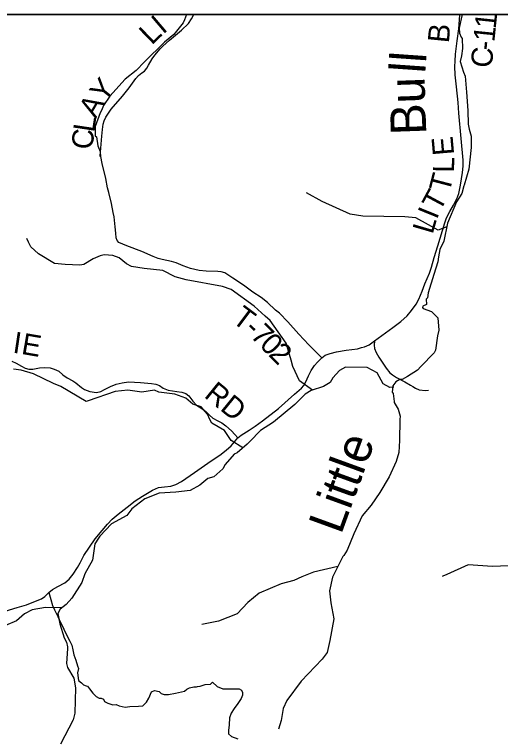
# Model space of a CAD drawing. Extents: x -1.8 to 75.7, y -2 to 25.
# Drawn here: x 45.252 to 46.551, y 20.577 to 22.512 of the extents above; entities that cross this region are included whole.
import ezdxf

# ---------------------------------------------------------------- set-up
doc = ezdxf.new("R2010")
doc.units = 0
for name, color, linetype in [('GM_X_County_Road', 7, 'Continuous'), ('GM_X_County_Road_Text', 7, 'Continuous'), ('GM_X_Minor_River', 7, 'Continuous'), ('GM_X_Minor_River_Text', 7, 'Continuous'), ('GM_X_Township', 7, 'Continuous'), ('GM_X_Township_Road', 7, 'Continuous'), ('GM_X_Township_Road_Text', 7, 'Continuous'), ('GM_X_Township_ROW', 7, 'Continuous'), ('SH_Data', 7, 'Continuous')]:
    doc.layers.add(name, color=color, linetype=linetype)

msp = doc.modelspace()

# ---------------------------------------------------------------- linework, layer by layer
at = {"layer": 'GM_X_County_Road'}
for points in [[(46.0729, 21.5947), (46.0824, 21.6016), (46.0951, 21.6065), (46.1123, 21.6108), (46.1385, 21.6148), (46.1687, 21.619), (46.1795, 21.6219), (46.1875, 21.6242), (46.1995, 21.6296), (46.2137, 21.6398), (46.2632, 21.6759), (46.2842, 21.6917), (46.3007, 21.7068), (46.3127, 21.7211), (46.325, 21.7379), (46.3323, 21.7511), (46.3408, 21.773), (46.3481, 21.7921), (46.3606, 21.8206), (46.3663, 21.8371), (46.3736, 21.8629), (46.3828, 21.8937), (46.4014, 21.955), (46.4063, 21.9683), (46.4148, 21.9859), (46.4245, 22.0029), (46.4337, 22.0194), (46.4391, 22.0336), (46.4438, 22.056), (46.4467, 22.0729), (46.4493, 22.0897), (46.4504, 22.1067), (46.4507, 22.1229), (46.445, 22.1809), (46.4396, 22.2484), (46.4372, 22.2767), (46.4328, 22.3191), (46.4297, 22.351), (46.4283, 22.3731), (46.429, 22.3877), (46.4306, 22.4057), (46.4351, 22.442), (46.4389, 22.4738), (46.442, 22.5101), (46.4422, 22.5121)], [(45.2266, 20.9177), (45.2587, 20.927), (45.2836, 20.9342), (45.3084, 20.944), (45.3243, 20.9507), (45.3331, 20.957), (45.3438, 20.9679), (45.3538, 20.9754), (45.3677, 20.9833), (45.3866, 20.9937), (45.398, 21.0033), (45.4091, 21.0165), (45.4203, 21.034), (45.4275, 21.047), (45.4376, 21.0662), (45.4519, 21.0886), (45.4677, 21.1107), (45.4862, 21.1336), (45.5007, 21.1499), (45.5131, 21.1639), (45.5289, 21.177), (45.5531, 21.1958), (45.5747, 21.2123), (45.5935, 21.2251), (45.6205, 21.2412), (45.6363, 21.2479), (45.6524, 21.2498), (45.6694, 21.2519), (45.6828, 21.2558), (45.6977, 21.2637), (45.7326, 21.2879), (45.777, 21.3191), (45.8008, 21.3349), (45.8177, 21.3479), (45.831, 21.3595), (45.8487, 21.3809), (45.8572, 21.3877), (45.8786, 21.4012), (45.8951, 21.4118), (45.9149, 21.4259), (45.9571, 21.4594), (46.0003, 21.4971), (46.0189, 21.5134), (46.0251, 21.5209), (46.0307, 21.5308), (46.0376, 21.5469), (46.0444, 21.5606), (46.0536, 21.574), (46.0611, 21.5827), (46.0729, 21.5947)]]:
    msp.add_lwpolyline(points, dxfattribs=at)
at = {"layer": 'GM_X_Minor_River'}
for points in [[(45.7119, 22.5121), (45.706, 22.498), (45.703, 22.49), (45.6773, 22.4584), (45.6524, 22.4382), (45.5991, 22.3856), (45.5769, 22.3624)], [(46.4481, 22.5121), (46.4454, 22.5006), (46.4401, 22.4751), (46.4409, 22.4622), (46.4458, 22.4511), (46.4485, 22.4481), (46.4493, 22.4211), (46.4459, 22.4017), (46.4429, 22.3865), (46.4516, 22.3577), (46.4558, 22.347), (46.46, 22.3048), (46.463, 22.2554), (46.4638, 22.2189), (46.4672, 22.206), (46.4722, 22.1867), (46.4718, 22.1563), (46.4658, 22.0988), (46.4534, 22.0559), (46.4526, 22.054), (46.4474, 22.0338), (46.4326, 22.011), (46.4089, 21.9543), (46.3995, 21.9067), (46.3882, 21.8839), (46.3851, 21.8649), (46.3833, 21.8508), (46.372, 21.817), (46.3576, 21.7686), (46.3554, 21.755), (46.352, 21.7515), (46.3528, 21.7375), (46.3433, 21.7329), (46.3422, 21.7287), (46.3441, 21.726), (46.366, 21.7181), (46.3827, 21.7014), (46.3861, 21.6687), (46.382, 21.6535), (46.3771, 21.6147), (46.3737, 21.6075), (46.3374, 21.5713), (46.3287, 21.5618), (46.3019, 21.5446), (46.2879, 21.5366), (46.2819, 21.537), (46.2706, 21.5305), (46.263, 21.5198), (46.2608, 21.5027), (46.2638, 21.4993), (46.2661, 21.4776), (46.2668, 21.475), (46.2774, 21.4571), (46.282, 21.4385), (46.2812, 21.4302), (46.2805, 21.3739), (46.2791, 21.3412), (46.2715, 21.3172), (46.253, 21.2765), (46.2281, 21.2343), (46.2051, 21.2008), (46.1813, 21.1726), (46.1583, 21.1242), (46.1406, 21.0809), (46.1315, 21.0664), (46.1296, 21.0634), (46.1221, 21.0496), (46.1016, 21.0086)], [(45.5769, 22.3624), (45.5478, 22.3391), (45.5066, 22.2938), (45.4893, 22.2687), (45.484, 22.2553), (45.4806, 22.2496), (45.4674, 22.2131), (45.4678, 22.1876), (45.4712, 22.185), (45.4746, 22.1611), (45.4807, 22.1462), (45.4803, 22.1337), (45.4807, 22.1337)], [(46.4069, 21.9444), (46.3838, 21.9355), (46.3244, 21.969), (46.295, 21.971), (46.1831, 21.9731), (46.1485, 21.9787), (46.0743, 22.0126), (46.0319, 22.0352)], [(46.048, 21.508), (46.0137, 21.533), (45.996, 21.5712), (45.9912, 21.5884), (45.9775, 21.6341), (45.9354, 21.6939), (45.9214, 21.7061), (45.892, 21.7325), (45.831, 21.7769), (45.8078, 21.7853), (45.7104, 21.8028), (45.6808, 21.8113), (45.648, 21.8276), (45.5983, 21.8337), (45.5649, 21.839), (45.5515, 21.8455), (45.5312, 21.8621), (45.5147, 21.8683), (45.4917, 21.8698), (45.4807, 21.8671), (45.4623, 21.8593), (45.4376, 21.8438), (45.4266, 21.8418), (45.387, 21.8439), (45.3591, 21.847), (45.3164, 21.8723), (45.2958, 21.8912), (45.289, 21.9035), (45.2851, 21.9132)], [(45.8616, 21.3538), (45.8308, 21.3733), (45.8128, 21.4008), (45.7793, 21.4197), (45.774, 21.4298), (45.7672, 21.4436), (45.7508, 21.4639), (45.7283, 21.4707), (45.7095, 21.4869), (45.68, 21.4973), (45.6375, 21.5032), (45.6259, 21.5078), (45.5925, 21.5028), (45.5793, 21.5043), (45.5545, 21.5081), (45.5211, 21.5046), (45.4485, 21.48), (45.4436, 21.4782), (45.3756, 21.5176), (45.3558, 21.5258), (45.3029, 21.5518), (45.27, 21.562), (45.2496, 21.5642)], [(46.2657, 21.5163), (46.2547, 21.5155), (46.2372, 21.5251), (46.2207, 21.5549), (46.1943, 21.569), (46.1361, 21.5698), (46.1204, 21.5611), (46.1024, 21.5408), (46.0956, 21.5289), (46.0779, 21.5177), (46.0447, 21.507), (46.0289, 21.4976), (46.0008, 21.4696), (45.9438, 21.4225), (45.9088, 21.4004), (45.8803, 21.3706), (45.8733, 21.3643), (45.8469, 21.3405), (45.8392, 21.3373), (45.8145, 21.3092), (45.8085, 21.298), (45.7848, 21.2767), (45.7684, 21.272), (45.7475, 21.254), (45.721, 21.2404), (45.6834, 21.2359), (45.6384, 21.2332), (45.6001, 21.2181), (45.5653, 21.1907), (45.5523, 21.1733), (45.5108, 21.1514), (45.4795, 21.1182), (45.4767, 21.113), (45.4668, 21.0977), (45.4602, 21.0535), (45.4398, 21.0173), (45.432, 20.9944), (45.4054, 20.9527), (45.3901, 20.935), (45.3742, 20.9226), (45.3675, 20.9114), (45.373, 20.8835), (45.3844, 20.8463), (45.3912, 20.8347), (45.3931, 20.8225), (45.3933, 20.8175), (45.3906, 20.7781), (45.3937, 20.7674), (45.4102, 20.7388), (45.4151, 20.7124), (45.4127, 20.6452), (45.4087, 20.6268), (45.3747, 20.5625)], [(47.1715, 21.1353), (47.0815, 21.1308), (47.0262, 21.1108), (47.0011, 21.1099), (46.9449, 21.1286), (46.9121, 21.1478), (46.8729, 21.1635), (46.8395, 21.1713), (46.8129, 21.1735), (46.7492, 21.1678), (46.7182, 21.149), (46.6173, 21.0764), (46.5939, 21.0542), (46.5716, 21.0389), (46.5287, 21.0368), (46.4638, 21.0418), (46.407, 21.0156), (46.3964, 21.0107), (46.3945, 21.0103)], [(46.1156, 21.0366), (46.0511, 21.0214), (46.0194, 21.0091), (45.9983, 20.9996), (45.9648, 20.9907), (45.9058, 20.966), (45.8752, 20.9404), (45.8467, 20.9106), (45.797, 20.8909), (45.7521, 20.8821)], [(46.1016, 21.0086), (46.0935, 20.9722), (46.0971, 20.9402), (46.1052, 20.8974), (46.0944, 20.8393), (46.087, 20.8076), (46.0736, 20.789), (46.0178, 20.7308), (45.9796, 20.6792), (45.9702, 20.6571), (45.9643, 20.6258), (45.9572, 20.6025)], [(45.3787, 20.9261), (45.3347, 20.9276), (45.2993, 20.9215), (45.2782, 20.9108), (45.2572, 20.8914), (45.2281, 20.879)]]:
    msp.add_lwpolyline(points, dxfattribs=at)
at = {"layer": 'GM_X_Township'}
msp.add_lwpolyline([(48.1876, 22.5121), (43.8002, 22.5121), (43.8002, 18.978)], dxfattribs=at)
at = {"layer": 'GM_X_Township_Road'}
for points in [[(46.0729, 21.5947), (46.0611, 21.6058), (46.0387, 21.6291), (46.0116, 21.6576), (45.9825, 21.6907), (45.96, 21.7142), (45.9494, 21.7222), (45.928, 21.7424), (45.9112, 21.7558), (45.8889, 21.7704), (45.8636, 21.7889), (45.8356, 21.8073), (45.8138, 21.8215), (45.8041, 21.8246), (45.795, 21.8251), (45.7641, 21.8262), (45.7452, 21.8275), (45.7219, 21.8331), (45.7028, 21.8404), (45.6841, 21.848), (45.6712, 21.852), (45.6466, 21.8571), (45.6354, 21.86), (45.6223, 21.8653), (45.5919, 21.8788), (45.5518, 21.8943), (45.531, 21.9028), (45.5266, 21.908), (45.5237, 21.9148), (45.5226, 21.9277), (45.5213, 21.9446), (45.5184, 21.9713), (45.5159, 21.983), (45.5115, 22.0073), (45.5044, 22.0361), (45.5008, 22.0492), (45.4962, 22.0739), (45.4866, 22.1137), (45.4826, 22.1326), (45.4817, 22.1439), (45.4835, 22.1657), (45.4855, 22.1868), (45.4871, 22.2045), (45.4891, 22.219), (45.4915, 22.2281), (45.4962, 22.2376), (45.503, 22.2487), (45.5106, 22.2592), (45.5406, 22.2938), (45.5586, 22.3165), (45.5764, 22.3412), (45.5835, 22.3492), (45.5921, 22.3563), (45.5992, 22.3609), (45.6055, 22.3685), (45.6103, 22.3767), (45.6199, 22.394), (45.6266, 22.4031), (45.6408, 22.42), (45.6479, 22.4278), (45.6657, 22.4431), (45.6981, 22.4705), (45.7165, 22.4882), (45.7248, 22.5004), (45.7313, 22.5121)], [(46.2137, 21.6398), (46.2125, 21.6287), (46.2142, 21.6197), (46.2179, 21.6091), (46.2255, 21.5964), (46.2453, 21.5667), (46.2552, 21.5549), (46.262, 21.5492), (46.2729, 21.5424), (46.2948, 21.5301), (46.3101, 21.5212)], [(45.2452, 21.5853), (45.2563, 21.5801), (45.2709, 21.5727), (45.2802, 21.5673), (45.2899, 21.5639), (45.301, 21.5642), (45.319, 21.5675), (45.3329, 21.5686), (45.3475, 21.5678), (45.3583, 21.5645), (45.3707, 21.5588), (45.3807, 21.5495), (45.3923, 21.5413), (45.4077, 21.5333), (45.4154, 21.5279), (45.4311, 21.5153), (45.4391, 21.5102), (45.453, 21.5044), (45.4712, 21.502), (45.4828, 21.5045), (45.4923, 21.5097), (45.5083, 21.5182), (45.5234, 21.5243), (45.5394, 21.5282), (45.5569, 21.5305), (45.589, 21.5285), (45.6183, 21.5259), (45.6296, 21.5238), (45.6391, 21.5202), (45.6489, 21.5133), (45.6623, 21.5081), (45.6855, 21.5043), (45.6993, 21.5025), (45.7098, 21.4989), (45.7173, 21.493), (45.7281, 21.4788), (45.7384, 21.4683), (45.7528, 21.4588), (45.7631, 21.4516), (45.7731, 21.441), (45.7818, 21.4336), (45.7952, 21.4264), (45.8055, 21.4205), (45.8163, 21.4125), (45.8317, 21.3999), (45.841, 21.3901), (45.8487, 21.3809)], [(45.3438, 20.9679), (45.3487, 20.9484), (45.3533, 20.9328), (45.3543, 20.9308)]]:
    msp.add_lwpolyline(points, dxfattribs=at)
at = {"layer": 'GM_X_Township_ROW'}
for points in [[(46.3101, 21.5212), (46.3163, 21.5176), (46.3236, 21.5139), (46.333, 21.5094), (46.3502, 21.507), (46.3585, 21.508)], [(45.3543, 20.9308), (45.3591, 20.9209), (45.3673, 20.9033), (45.3759, 20.8854), (45.3808, 20.8754), (45.3863, 20.8633), (45.3994, 20.8375), (45.4055, 20.8268), (45.4074, 20.8147), (45.4104, 20.8006), (45.4159, 20.7865), (45.4206, 20.7713), (45.423, 20.7648), (45.4204, 20.7525), (45.423, 20.7326), (45.4308, 20.7261), (45.4359, 20.7205), (45.4434, 20.7183), (45.4473, 20.7169), (45.4521, 20.7098), (45.4611, 20.6984), (45.4704, 20.69), (45.4782, 20.6853), (45.4833, 20.6848), (45.4895, 20.6821), (45.4922, 20.6758), (45.5014, 20.6717), (45.5144, 20.667), (45.5233, 20.668), (45.5318, 20.6649), (45.5472, 20.6608), (45.5598, 20.6628), (45.5828, 20.6634), (45.5951, 20.6643), (45.6047, 20.6743), (45.6106, 20.6847), (45.6179, 20.7025), (45.6264, 20.7053), (45.6382, 20.703), (45.644, 20.6973), (45.6516, 20.6953), (45.6631, 20.6953), (45.6825, 20.6987), (45.7065, 20.704), (45.7121, 20.7093), (45.7197, 20.7129), (45.7312, 20.7155), (45.7379, 20.7154), (45.7412, 20.7161), (45.7479, 20.7174), (45.7614, 20.7218), (45.7753, 20.7229), (45.7807, 20.7277), (45.7935, 20.7164), (45.8083, 20.7105), (45.8397, 20.7103), (45.8525, 20.7101), (45.8584, 20.7068), (45.8614, 20.7003), (45.8615, 20.6934), (45.8573, 20.684), (45.8491, 20.6708), (45.8389, 20.6578), (45.8311, 20.645), (45.8267, 20.6324), (45.8253, 20.6143), (45.8238, 20.5987), (45.8238, 20.59), (45.8313, 20.5823), (45.8484, 20.5767)]]:
    msp.add_lwpolyline(points, dxfattribs=at)
at = {"layer": 'SH_Data'}
msp.add_line((43.8002, 22.5121), (50.6002, 22.5121), dxfattribs=at)
msp.add_line((43.8002, 22.5121), (50.6002, 22.5121), dxfattribs=at)

# ---------------------------------------------------------------- texts
at = {"layer": 'GM_X_County_Road_Text'}
for s, rotation, p in [('1', 83.9313, (46.5375, 22.4721)), ('B', 84.41, (46.4123, 22.4343)), ('1', 84.1509, (46.534, 22.4373)), ('-', 84.2059, (46.5316, 22.4141)), ('C', 84.2255, (46.5269, 22.3677)), ('E', 94.925, (46.4268, 22.1377)), ('L', 89.1621, (46.4264, 22.0891)), ('T', 75.355, (46.4137, 22.0335)), ('T', 61.7299, (46.3883, 21.9826)), ('I', 67.8956, (46.3802, 21.9624)), ('L', 73.795, (46.3689, 21.923))]:
    msp.add_text(s, height=0.0568, rotation=rotation, dxfattribs=at).set_placement(p)
at = {"layer": 'GM_X_Minor_River_Text'}
for s, height, rotation, p in [('ll', 0.0947, 85.9995, (46.3493, 22.3532)), ('Bu', 0.0947, 91.9992, (46.3525, 22.1914)), ('Little ', 0.09471, 70.0041, (46.1244, 21.12))]:
    msp.add_text(s, height=height, rotation=rotation, dxfattribs=at).set_placement(p)
at = {"layer": 'GM_X_Township_Road_Text'}
for s, height, rotation, p in [('I', 0.0568, 40.3833, (45.6483, 22.4576)), ('L', 0.0568, 44.0075, (45.6184, 22.4287)), ('Y', 0.0568, 51.5518, (45.4931, 22.2734)), ('A', 0.0568, 59.4748, (45.4689, 22.2321)), ('L', 0.0568, 81.4353, (45.4645, 22.1954)), ('C', 0.0568, 85.092, (45.4606, 22.1499)), ('T', 0.0568, 323.1138, (45.8303, 21.692)), ('7', 0.0568, 314.4793, (45.8797, 21.6521)), ('-', 0.0568, 317.0427, (45.8631, 21.6675)), ('I', 0.0568, 351.5785, (45.2453, 21.6086)), ('E', 0.0568, 350.3918, (45.2681, 21.6053)), ('0', 0.0568, 314.1776, (45.9041, 21.6272)), ('2', 0.0568, 314.1223, (45.9285, 21.6021)), ('RD', 0.05682, 320.9542, (45.7561, 21.4911))]:
    msp.add_text(s, height=height, rotation=rotation, dxfattribs=at).set_placement(p)

doc.saveas('drawing.dxf')
